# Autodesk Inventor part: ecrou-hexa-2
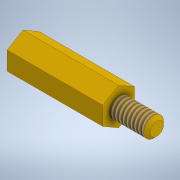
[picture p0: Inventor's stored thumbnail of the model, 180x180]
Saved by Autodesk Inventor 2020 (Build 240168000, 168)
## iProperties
Created: 2021-10
Part Number: ecrou-hexa-2
Material: Générique
Document SubType Name: Modeling
Designer: bruno
Density: 1 g/cm^3
Appearance: Or
Author: bruno
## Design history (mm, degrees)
sketch "Esquisse1"
  geometry: L1 (-2.887, 0)-(-1.443, 2.5); L2 (-1.443, 2.5)-(1.443, 2.5); L3 (1.443, 2.5)-(2.887, 0); L4 (2.887, 0)-(1.443, -2.5); L5 (1.443, -2.5)-(-1.443, -2.5); L6 (-1.443, -2.5)-(-2.887, 0); C1 r 1.5 at (0, 0); 2 further points
  constraints: 12 end point, 2 coincident, 1 centre point, 13 other
  dimensions: "d0" = 5 distance between parallel lines of L2 L5; "d1" = 3 diameter of C1
extrude "Extrusion1" new body sketch "Esquisse1" distance "d2" = 15; taper "d3" = 0 deg
feature "Filetage1" dims "d4" = 17, "d5" = 0
sketch "Esquisse2"
  geometry: C1 r 1.541 at (0, 0); 1 further point
  constraints: 1 centre point, 1 coincident
extrude "Extrusion2" join sketch "Esquisse2" distance "d6" = 6; taper "d7" = 0 deg
chamfer "Chanfrein1" distance "d8" = 0.5; stored, may be unused: second distance "d9" = 2, angle "d10" = 45 deg
feature "Filetage2" dims "d11" = 5.5, "d12" = 0
node "Solide1"
